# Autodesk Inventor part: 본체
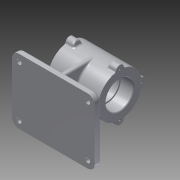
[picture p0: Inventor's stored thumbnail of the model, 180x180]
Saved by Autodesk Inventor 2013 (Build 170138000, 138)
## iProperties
Created: 2015-12
Part Number: 본체
Material: 알루미늄 6061
Document SubType Name: Modeling
Designer: user
Density: 2.71 g/cm^3
Mass: 1165.02 g
Surface Area: 814.926 cm^2
Volume: 429.895 cm^3
Author: user
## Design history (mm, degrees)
sketch "스케치1"
  geometry: L1 (-42.5, 0)-(42.5, 0); L2 (-42.5, 0)-(-42.5, 37); L3 (-42.5, 37)-(42.5, 37); L4 (42.5, 37)-(42.5, 0); L5 (-42.5, 23.5)-(-20.5, 23.5); L6 (-20.5, 23.5)-(-20.5, 21); L7 (-20.5, 21)-(20.5, 21); L8 (20.5, 21)-(20.5, 23.5); L9 (20.5, 23.5)-(42.5, 23.5); 2 further points
  constraints: 18 end point, 5 perpendicular, 3 parallel, 2 midpoint, 2 point on line, 1 coincident, 1 horizontal
  dimensions: "d0" = 85 distance of L1.start L1.end; "d1" = 74 diameter of L3 L1; "d2" = 47 diameter of L5 L1; "d3" = 42 diameter of L7 L1; "d4" = 47 diameter of L9 L1; "d5" = 22 distance between parallel lines of L8 L4; "d6" = 22 distance between parallel lines of L6 L2
revolve "회전1" stored, may be unused: angle "d7" = 90 deg
sketch "스케치2"
  geometry: C1 r 7 at (0, 37); 1 further point
  constraints: 2 vertical alignment, 1 centre point, 1 other
  dimensions: "d8" = 14 diameter of C1
extrude "돌출1" join sketch "스케치2" distance "d9" = 15; taper "d10" = 0 deg
sketch "스케치3"
  geometry: L1 (-42.5, 36.338)-(-27.5, 36.338) reference; L2 (-42.5, 36.338)-(-42.5, 36.338) reference; L3 (-27.5, 36.338)-(-42.5, 36.338) reference; L4 (-27.5, 36.338)-(-27.5, 36.338) reference; L5 (-42.5, 36.338)-(-42.5, 44) reference; L6 (-27.5, 36.338)-(-27.5, 44) reference; L7 (-42.5, 44)-(-27.5, 44) reference; L8 (-27.5, 36.338)-(42.5, 36.338); L9 (-27.5, 36.338)-(-30.289, 44); L10 (42.5, -37)-(42.5, 37) reference; L11 (-30.289, 44)-(-27.5, 44); L12 (-27.5, 44)-(-27.5, 36.338); 2 further points
  constraints: 8 end point, 2 point on line, 1 collinear, 1 perpendicular
  dimensions: "d78" = 110 deg angle of L9 L8
  node "투영된 루프1"
node "작업 평면1"
sketch "스케치5"
  geometry: L1 (-80, 55)-(60, 55); L2 (60, 55)-(60, -55); L3 (60, -55)-(-80, -55); L4 (-80, -55)-(-80, 55); 10 further points; 4 other entities
  constraints: 8 end point, 2 coincident, 2 parallel, 2 vertical alignment, 1 horizontal, 1 horizontal alignment, 1 midpoint, 1 perpendicular
  dimensions: "d28" = 140 distance of L2.end L3.end; "d29" = 110 distance of L1.end L2.end; "d30" = 37.5 dimension on L4
extrude "돌출3" join sketch "스케치5" distance "d31" = 10; taper "d32" = 0 deg
sketch "스케치6"
  geometry: L1 (-60, -55)-(80, -55) reference; L2 (80, -55)-(80, 55) reference; L3 (80, 55)-(-60, 55) reference; C1 r 4 at (68, -43); C2 r 4 at (68, 43); C3 r 4 at (-48, -43); C4 r 4 at (-48, 43); 1 further point
  constraints: 4 centre point, 2 horizontal alignment, 2 vertical alignment
  dimensions: "d33" = 8 diameter of C1; "d34" = 8 diameter of C2; "d35" = 8 diameter of C3; "d36" = 8 diameter of C4; "d37" = 116 distance of C3.centre C1.centre; "d38" = 12 distance from line of L2 C1.centre; "d39" = 12 distance from line of L1 C1.centre; "d40" = 12 distance from line of L3 C2.centre
extrude "돌출4" cut sketch "스케치6" stored distance "d41" = 10; taper "d42" = 0 deg
chamfer "모따기1" distance "d43" = 1; stored, may be unused: second distance "d44" = 2, angle "d45" = 45 deg
sketch "스케치7"
  geometry: L1 (4, -37)-(-4, -37); L2 (-4, -37)-(-4, 37); L3 (-4, 37)-(4, 37); L4 (4, 37)-(4, -37); 3 further points
  constraints: 8 end point, 2 midpoint, 2 parallel, 1 horizontal, 1 horizontal alignment, 1 perpendicular, 1 vertical alignment
  dimensions: "d52" = 8 distance of L2.end L3.end; "d53" = 74 distance of L1.end L2.end
extrude "돌출5" join sketch "스케치7" stored distance "d54" = 10; taper "d55" = 0 deg
sketch "스케치8"
  geometry: L1 (-60, -70)-(80, -70) reference; L2 (25, -70)-(-25, -70); L3 (4, -70)-(-4, -70) reference; L4 (25, -70)-(19.978, -29.101); L5 (19.978, -29.101)-(-19.978, -29.101); L6 (-19.978, -29.101)-(-25, -70); 3 further points
  constraints: 8 end point, 2 midpoint, 2 point on line, 1 coincident, 1 parallel
  dimensions: "d56" = 50 distance of L2.start L2.end; "d57" = 97 deg angle of L4 L1; "d59" = 97 deg angle of L6 L1; "d61" = 39.95659 distance of L4.end L5.end
extrude "돌출6" join sketch "스케치8" stored distance "d62" = 12; taper "d63" = 0 deg
node "작업 평면3"
  node "작업 평면2"
fillet "모깎기1" dims "d68" = 12
chamfer "모따기2" distance "d69" = 1; stored, may be unused: second distance "d70" = 2, angle "d71" = 45 deg
fillet "모깎기2" dims "d72" = 0.3
fillet "모깎기3" dims "d73" = 3
fillet "모깎기6" dims "d76" = 3
fillet "모깎기7" dims "d77" = 3
extrude "돌출7" cut sketch "스케치3" stored distance "d79" = 30; taper "d80" = 0 deg
revolve "회전2" stored, may be unused: angle "d81" = 90 deg
chamfer "모따기3" distance "d82" = 1; stored, may be unused: second distance "d83" = 2, angle "d84" = 45 deg
revolve "회전3" stored, may be unused: angle "d95" = 90 deg
chamfer "모따기4" distance "d96" = 1; stored, may be unused: second distance "d97" = 2, angle "d98" = 45 deg
sketch "스케치12"
  geometry: A1 r 7 centre (0, 0) between (6.969, -0.662) and (-6.969, -0.662) reference; 1 further point
  constraints: 1 coincident
hole "구멍3" sketch "스케치12" at (0, 0) diameter "d99" = 3.242; stored, may be unused: countersink angle "d103" = 90 deg, drill point angle "d105" = 118 deg; dims "d100" = 9, "d101" = 4, "d102" = 2, "d104" = 11
fillet "모깎기8" dims "d109" = 3
fillet "모깎기9" dims "d110" = 3
sketch "스케치13"
  geometry: L1 (-42.5, 18.921)-(-42.5, -18.921) reference; L2 (42.5, 18.921)-(42.5, -18.921) reference; 3 further points
  constraints: 1 horizontal alignment, 1 midpoint, 1 other
  dimensions: "d113" = 42.5 distance from line of point (0, 0) L1
feature "엠보싱3" sketch "스케치13" dims "d0" = 85, "d1" = 74, "d2" = 47, "d3" = 42, "d4" = 47, "d5" = 22, "d6" = 22, "d114" = 0.5, "d115" = 0
node "솔리드1"
pattern_circular "원형 패턴2" dims angle "d93" = 360 deg
mirror "대칭2"
pattern_circular "원형 패턴3" dims angle "d107" = 360 deg
mirror "대칭3"
other parameters: "d64" = 45 deg
